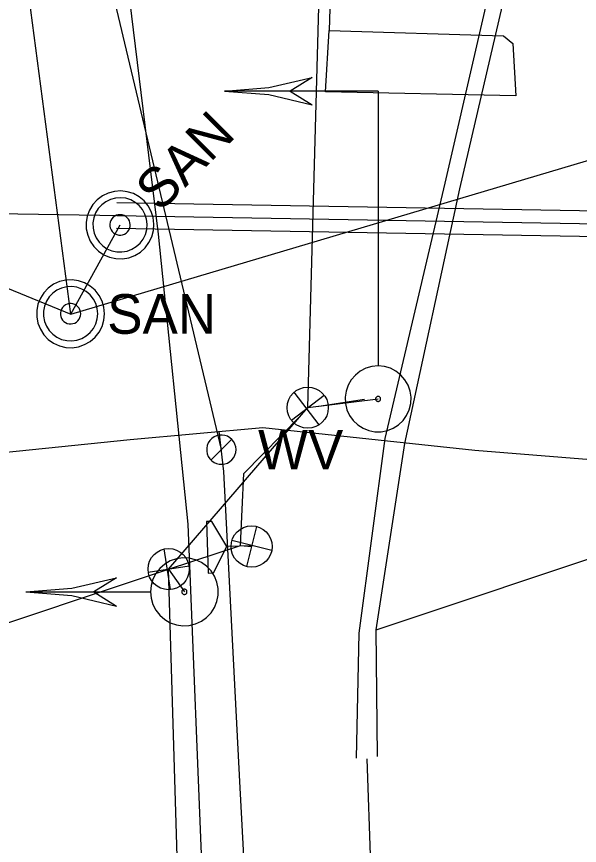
# Model space of a CAD drawing. Extents: x 596028 to 606371, y 330010 to 403088.
# Drawn here: x 605075.1 to 605129.8, y 337934.3 to 338014.8 of the extents above; entities that cross this region are included whole.
import ezdxf

# ---------------------------------------------------------------- set-up
doc = ezdxf.new("R2010")
doc.units = 0
for name, color, linetype in [('E_SIG', 7, 'Continuous'), ('E_SIG_Conduit', 7, 'Continuous'), ('E_UTL_E_UG', 7, 'Continuous'), ('E_UTL_FO_UG', 7, 'Continuous'), ('E_UTL_G_UG', 7, 'Continuous'), ('E_UTL_Loop_UG', 7, 'Continuous'), ('E_UTL_SAN_MH', 7, 'Continuous'), ('E_UTL_SAN_UG', 7, 'Continuous'), ('E_UTL_SAN_UG_MMSD', 7, 'Continuous'), ('E_UTL_SAN_UG_OUTER_LIMITS', 7, 'Continuous'), ('E_UTL_TV_UG', 7, 'Continuous'), ('E_UTL_W', 7, 'Continuous'), ('E_UTL_W_UG', 7, 'Continuous')]:
    doc.layers.add(name, color=color, linetype=linetype)

# ---------------------------------------------------------------- blocks, each defined once
blk = doc.blocks.new('_U316')
at = {"layer": 'E_SIG'}
for p, q in [((0, 6.1), (0, -6.1)), ((-6.09, 0.4), (6.1, 0.4))]:
    blk.add_line(p, q, dxfattribs=at)
blk.add_circle((0, 0.01), 6.1, dxfattribs=at)
blk = doc.blocks.new('_U317')
at = {"layer": 'E_SIG'}
for p, q in [((0, 6.1), (0, -6.1)), ((-6.09, 0.4), (6.1, 0.4))]:
    blk.add_line(p, q, dxfattribs=at)
blk.add_circle((0, 0.01), 6.1, dxfattribs=at)
blk = doc.blocks.new('_U310')
at = {"layer": 'E_SIG'}
for p, q in [((0, 6.1), (0, -6.1)), ((-6.09, 0.4), (6.1, 0.4))]:
    blk.add_line(p, q, dxfattribs=at)
blk.add_circle((0, 0.01), 6.1, dxfattribs=at)

msp = doc.modelspace()

# ---------------------------------------------------------------- linework, layer by layer
at = {"layer": 'E_SIG'}
msp.add_line((605097.976, 337963.419), (605095.576, 337963.336), dxfattribs=at)
for points in [[(605095.332, 338007.579), (605099.655, 338007.914), (605103.873, 338008.913)], [(605103.873, 338008.916), (605101.737, 338007.579)], [(605095.332, 338007.579), (605099.655, 338007.243), (605103.873, 338006.244)], [(605110.278, 338007.579), (605095.333, 338007.579)], [(605101.737, 338007.579), (605103.873, 338006.242)], [(605110.278, 338007.579), (605110.278, 337980.94)], [(605110.278, 338000.105), (605110.278, 338000.105)], [(605110.279, 337980.888), (605109.673, 337980.83), (605109.089, 337980.658), (605108.548, 337980.379), (605108.069, 337980.003), (605107.67, 337979.543), (605107.366, 337979.015), (605107.167, 337978.44), (605107.08, 337977.837), (605107.109, 337977.229), (605107.253, 337976.637), (605107.505, 337976.083), (605107.859, 337975.587), (605108.299, 337975.167), (605108.812, 337974.838), (605109.377, 337974.611), (605109.975, 337974.496), (605110.584, 337974.496), (605111.182, 337974.611), (605111.747, 337974.838), (605112.259, 337975.167), (605112.7, 337975.587), (605113.053, 337976.083), (605113.306, 337976.637), (605113.45, 337977.229), (605113.479, 337977.837), (605113.392, 337978.44), (605113.193, 337979.015), (605112.888, 337979.543), (605112.49, 337980.003), (605112.011, 337980.379), (605111.47, 337980.658), (605110.885, 337980.83), (605110.279, 337980.888)], [(605110.279, 337977.93), (605110.233, 337977.925), (605110.188, 337977.912), (605110.147, 337977.891), (605110.11, 337977.862), (605110.08, 337977.827), (605110.056, 337977.786), (605110.041, 337977.742), (605110.035, 337977.696), (605110.037, 337977.65), (605110.048, 337977.605), (605110.067, 337977.562), (605110.094, 337977.524), (605110.128, 337977.492), (605110.167, 337977.467), (605110.21, 337977.45), (605110.256, 337977.441), (605110.303, 337977.441), (605110.348, 337977.45), (605110.392, 337977.467), (605110.431, 337977.492), (605110.464, 337977.524), (605110.491, 337977.562), (605110.511, 337977.605), (605110.522, 337977.65), (605110.524, 337977.696), (605110.517, 337977.742), (605110.502, 337977.786), (605110.479, 337977.827), (605110.448, 337977.862), (605110.412, 337977.891), (605110.37, 337977.912), (605110.326, 337977.925), (605110.279, 337977.93)], [(605088.149, 337958.945), (605088.209, 337958.32), (605088.385, 337957.718), (605088.673, 337957.16), (605089.061, 337956.667), (605089.535, 337956.256), (605090.078, 337955.943), (605090.671, 337955.738), (605091.292, 337955.648), (605091.919, 337955.678), (605092.528, 337955.826), (605093.099, 337956.087), (605093.61, 337956.451), (605094.043, 337956.905), (605094.382, 337957.432), (605094.615, 337958.015), (605094.734, 337958.631), (605094.734, 337959.258), (605094.615, 337959.874), (605094.382, 337960.457), (605094.043, 337960.985), (605093.61, 337961.439), (605093.099, 337961.802), (605092.528, 337962.063), (605091.919, 337962.211), (605091.292, 337962.241), (605090.671, 337962.152), (605090.078, 337961.946), (605089.535, 337961.633), (605089.061, 337961.222), (605088.673, 337960.729), (605088.385, 337960.171), (605088.209, 337959.569), (605088.149, 337958.945)], [(605076.049, 337958.945), (605080.502, 337959.29), (605084.849, 337960.32)], [(605084.849, 337960.318), (605082.648, 337958.946)], [(605076.049, 337958.945), (605080.502, 337958.599), (605084.849, 337957.57)], [(605076.05, 337958.946), (605088.091, 337958.946)], [(605082.648, 337958.946), (605084.849, 337957.569)], [(605091.197, 337958.945), (605091.201, 337958.897), (605091.215, 337958.851), (605091.237, 337958.808), (605091.266, 337958.77), (605091.303, 337958.739), (605091.344, 337958.715), (605091.39, 337958.699), (605091.437, 337958.692), (605091.485, 337958.695), (605091.532, 337958.706), (605091.575, 337958.726), (605091.614, 337958.754), (605091.647, 337958.789), (605091.673, 337958.829), (605091.691, 337958.873), (605091.7, 337958.921), (605091.7, 337958.969), (605091.691, 337959.016), (605091.673, 337959.06), (605091.647, 337959.101), (605091.614, 337959.135), (605091.575, 337959.163), (605091.532, 337959.183), (605091.485, 337959.194), (605091.437, 337959.197), (605091.39, 337959.19), (605091.344, 337959.174), (605091.303, 337959.15), (605091.266, 337959.119), (605091.237, 337959.081), (605091.215, 337959.038), (605091.201, 337958.992), (605091.197, 337958.945)]]:
    msp.add_lwpolyline(points, dxfattribs=at)
msp.add_lwpolyline([(605094.116, 337965.79), (605093.595, 337965.772), (605093.769, 337960.769), (605094.289, 337960.787), (605095.577, 337963.336)], close=True, dxfattribs=at)
at = {"layer": 'E_SIG_Conduit'}
for points in [[(605103.44, 337976.834), (605105.21, 338040.564)], [(605103.44, 337976.834), (605110.28, 337977.684)], [(605104.502, 337976.967), (605108.946, 337977.652)], [(605089.92, 337961.154), (605103.44, 337976.834)], [(605096.91, 337963.454), (605097.23, 337970.434), (605102.7, 337976.014), (605103.44, 337976.834)], [(605089.92, 337961.154), (605096.91, 337963.454), (605097.98, 337963.344)], [(605047.35, 337946.974), (605089.92, 337961.154)], [(605089.92, 337961.154), (605091.45, 337958.944)]]:
    msp.add_lwpolyline(points, dxfattribs=at)
at = {"layer": 'E_UTL_E_UG'}
msp.add_lwpolyline([(605091.971, 337892.476), (605089.92, 337961.154)], dxfattribs=at)
at = {"layer": 'E_UTL_FO_UG'}
msp.add_lwpolyline([(605110.1, 337955.254), (605134.845, 337963.521)], dxfattribs=at)
at = {"layer": 'E_UTL_G_UG'}
for points in [[(604985.13, 338025.804), (604984.31, 338018.124), (604982.82, 338008.484), (604982.14, 337990.424), (604982.27, 337979.474), (604987, 337975.814), (604995.42, 337975.544), (605011.51, 337976.254), (605020.99, 337971.804), (605053.36, 337969.444), (605062.73, 337971.354), (605086.18, 337973.754), (605099.06, 337974.904), (605119.67, 337972.714), (605158.32, 337969.584), (605188.11, 337968.304), (605207.41, 337968.584), (605224.32, 337967.714), (605236.94, 337968.084), (605244.48, 337969.024), (605249.449, 337969.464), (605249.239, 337972.164), (605249.239, 337972.534)], [(605094.31, 337912.064), (605093.27, 337929.444), (605091.82, 337965.534), (605088.93, 337993.674), (605086.15, 338016.474)]]:
    msp.add_lwpolyline(points, dxfattribs=at)
at = {"layer": 'E_UTL_Loop_UG'}
msp.add_line((605105.64, 338018.244), (605105.53, 338013.454), dxfattribs=at)
msp.add_lwpolyline([(605105.53, 338013.454), (605122.47, 338012.934), (605123.39, 338012.194), (605123.65, 338007.124), (605105.18, 338007.504)], close=True, dxfattribs=at)
at = {"layer": 'E_UTL_SAN_MH'}
for points in [[(605087.524, 337996.919), (605087.04, 337997.319), (605086.489, 337997.62), (605085.892, 337997.811), (605085.269, 337997.885), (605084.643, 337997.84), (605084.037, 337997.678), (605083.473, 337997.404), (605082.97, 337997.028), (605082.548, 337996.564), (605082.222, 337996.028), (605082.003, 337995.44), (605081.899, 337994.821), (605081.914, 337994.194), (605082.047, 337993.581), (605082.294, 337993.004), (605082.646, 337992.485), (605083.089, 337992.041), (605083.609, 337991.69), (605084.185, 337991.443), (605084.798, 337991.309), (605085.426, 337991.294), (605086.044, 337991.398), (605086.632, 337991.618), (605087.168, 337991.944), (605087.632, 337992.366), (605088.008, 337992.868), (605088.282, 337993.433), (605088.445, 337994.039), (605088.489, 337994.665), (605088.415, 337995.287), (605088.224, 337995.885), (605087.923, 337996.436), (605087.524, 337996.919)], [(605087.057, 337996.453), (605086.67, 337996.772), (605086.229, 337997.013), (605085.751, 337997.166), (605085.253, 337997.225), (605084.752, 337997.189), (605084.268, 337997.06), (605083.816, 337996.84), (605083.414, 337996.539), (605083.077, 337996.168), (605082.816, 337995.74), (605082.64, 337995.269), (605082.557, 337994.774), (605082.569, 337994.273), (605082.676, 337993.782), (605082.873, 337993.321), (605083.154, 337992.905), (605083.509, 337992.55), (605083.925, 337992.269), (605084.386, 337992.071), (605084.877, 337991.965), (605085.379, 337991.953), (605085.873, 337992.036), (605086.344, 337992.211), (605086.772, 337992.473), (605087.144, 337992.81), (605087.444, 337993.212), (605087.664, 337993.663), (605087.794, 337994.148), (605087.829, 337994.649), (605087.77, 337995.147), (605087.617, 337995.625), (605087.377, 337996.066), (605087.057, 337996.453)], [(605085.89, 337995.286), (605085.745, 337995.406), (605085.58, 337995.496), (605085.401, 337995.553), (605085.214, 337995.576), (605085.026, 337995.562), (605084.844, 337995.514), (605084.675, 337995.431), (605084.524, 337995.319), (605084.398, 337995.179), (605084.3, 337995.019), (605084.234, 337994.842), (605084.203, 337994.657), (605084.207, 337994.468), (605084.247, 337994.285), (605084.321, 337994.112), (605084.427, 337993.956), (605084.56, 337993.823), (605084.716, 337993.717), (605084.889, 337993.643), (605085.073, 337993.603), (605085.261, 337993.599), (605085.446, 337993.63), (605085.623, 337993.696), (605085.783, 337993.793), (605085.923, 337993.92), (605086.036, 337994.071), (605086.118, 337994.24), (605086.166, 337994.422), (605086.18, 337994.61), (605086.158, 337994.796), (605086.1, 337994.976), (605086.01, 337995.141), (605085.89, 337995.286)], [(605083.682, 337985.955), (605083.622, 337986.58), (605083.445, 337987.182), (605083.158, 337987.739), (605082.77, 337988.232), (605082.296, 337988.643), (605081.752, 337988.957), (605081.16, 337989.162), (605080.539, 337989.251), (605079.912, 337989.222), (605079.302, 337989.074), (605078.732, 337988.813), (605078.22, 337988.449), (605077.788, 337987.995), (605077.448, 337987.467), (605077.215, 337986.885), (605077.096, 337986.269), (605077.096, 337985.641), (605077.215, 337985.025), (605077.448, 337984.443), (605077.788, 337983.915), (605078.22, 337983.461), (605078.732, 337983.097), (605079.302, 337982.837), (605079.912, 337982.689), (605080.539, 337982.659), (605081.16, 337982.748), (605081.752, 337982.953), (605082.296, 337983.267), (605082.77, 337983.678), (605083.158, 337984.171), (605083.445, 337984.729), (605083.622, 337985.331), (605083.682, 337985.955)], [(605083.022, 337985.955), (605082.974, 337986.455), (605082.832, 337986.936), (605082.602, 337987.382), (605082.292, 337987.777), (605081.913, 337988.106), (605081.478, 337988.357), (605081.004, 337988.521), (605080.507, 337988.592), (605080.006, 337988.568), (605079.518, 337988.45), (605079.062, 337988.241), (605078.653, 337987.95), (605078.306, 337987.587), (605078.035, 337987.165), (605077.848, 337986.699), (605077.753, 337986.206), (605077.753, 337985.704), (605077.848, 337985.211), (605078.035, 337984.745), (605078.306, 337984.323), (605078.653, 337983.96), (605079.062, 337983.669), (605079.518, 337983.46), (605080.006, 337983.342), (605080.507, 337983.318), (605081.004, 337983.39), (605081.478, 337983.554), (605081.913, 337983.805), (605082.292, 337984.133), (605082.602, 337984.528), (605082.832, 337984.974), (605082.974, 337985.456), (605083.022, 337985.955)], [(605081.372, 337985.955), (605081.354, 337986.143), (605081.301, 337986.323), (605081.214, 337986.49), (605081.098, 337986.638), (605080.956, 337986.762), (605080.793, 337986.856), (605080.615, 337986.917), (605080.429, 337986.944), (605080.241, 337986.935), (605080.058, 337986.891), (605079.887, 337986.813), (605079.733, 337986.703), (605079.603, 337986.567), (605079.502, 337986.409), (605079.432, 337986.234), (605079.396, 337986.049), (605079.396, 337985.861), (605079.432, 337985.676), (605079.502, 337985.502), (605079.603, 337985.343), (605079.733, 337985.207), (605079.887, 337985.098), (605080.058, 337985.02), (605080.241, 337984.975), (605080.429, 337984.966), (605080.615, 337984.993), (605080.793, 337985.055), (605080.956, 337985.149), (605081.098, 337985.272), (605081.214, 337985.42), (605081.301, 337985.587), (605081.354, 337985.768), (605081.372, 337985.955)]]:
    msp.add_lwpolyline(points, dxfattribs=at)
at = {"layer": 'E_UTL_SAN_UG'}
for q in [(605067.643, 338083.076), (605153.517, 338007.635), (605085.19, 337994.584)]:
    msp.add_line((605080.423, 337985.919), q, dxfattribs=at)
msp.add_lwpolyline([(605046.371, 337999.856), (605080.423, 337985.919)], dxfattribs=at)
at = {"layer": 'E_UTL_SAN_UG_MMSD'}
for p, q in [((604679.668, 338002.431), (605085.205, 337995.499)), ((605084.871, 337995.504), (605699.33, 337985.001))]:
    msp.add_line(p, q, dxfattribs=at)
at = {"layer": 'E_UTL_SAN_UG_OUTER_LIMITS'}
for p, q in [((605084.892, 337996.754), (605699.351, 337986.251)), ((605084.849, 337994.255), (605699.309, 337983.751))]:
    msp.add_line(p, q, dxfattribs=at)
at = {"layer": 'E_UTL_TV_UG'}
msp.add_line((605117.511, 337719.769), (605109.201, 337942.73), dxfattribs=at)
for points in [[(605108.19, 337942.804), (605108.43, 337954.924), (605110.98, 337973.854), (605116.8, 337998.644), (605123.14, 338026.194), (605126.02, 338040.874), (605126, 338040.904), (605125.28, 338046.954)], [(605110.21, 337942.944), (605110.1, 337955.254), (605112.87, 337973.354), (605118.22, 337998.074), (605124.68, 338025.804), (605129.14, 338040.474), (605128.12, 338046.924)]]:
    msp.add_lwpolyline(points, dxfattribs=at)
at = {"layer": 'E_UTL_W'}
for points in [[(605096.466, 337972.754), (605096.44, 337973.024), (605096.364, 337973.284), (605096.239, 337973.525), (605096.072, 337973.738), (605095.867, 337973.916), (605095.632, 337974.051), (605095.376, 337974.14), (605095.108, 337974.178), (605094.837, 337974.166), (605094.574, 337974.102), (605094.327, 337973.989), (605094.106, 337973.832), (605093.919, 337973.636), (605093.773, 337973.408), (605093.672, 337973.156), (605093.62, 337972.89), (605093.62, 337972.619), (605093.672, 337972.352), (605093.773, 337972.101), (605093.919, 337971.873), (605094.106, 337971.677), (605094.327, 337971.519), (605094.574, 337971.407), (605094.837, 337971.343), (605095.108, 337971.33), (605095.376, 337971.368), (605095.632, 337971.457), (605095.867, 337971.593), (605096.072, 337971.77), (605096.239, 337971.983), (605096.364, 337972.224), (605096.44, 337972.484), (605096.466, 337972.754)], [(605094.032, 337971.746), (605096.048, 337973.762)]]:
    msp.add_lwpolyline(points, dxfattribs=at)
at = {"layer": 'E_UTL_W_UG'}
for points in [[(605095.04, 337972.754), (605084.561, 338016.897)], [(605099.19, 337892.984), (605098.07, 337917.504), (605096.85, 337940.534), (605095.29, 337970.624), (605094.83, 337974.544)]]:
    msp.add_lwpolyline(points, dxfattribs=at)

# ---------------------------------------------------------------- block references
at = {"layer": 'E_SIG', "xscale": 0.3280833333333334, "yscale": 0.3280833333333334, "rotation": -14.081618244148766}
msp.add_blockref('_U310', (605097.98, 337963.344), dxfattribs=at)
at = {"layer": 'E_SIG_Conduit', "xscale": 0.32808333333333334}
for name, p, yscale, rotation in [('_U316', (605103.44, 337976.834), 0.32808333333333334, 127.52190590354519), ('_U317', (605089.92, 337961.154), 0.3280833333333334, 98.72489939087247)]:
    msp.add_blockref(name, p, dxfattribs=dict(at, yscale=yscale, rotation=rotation))

# ---------------------------------------------------------------- texts
at = {"layer": 'E_UTL_SAN_MH'}
msp.add_text('SAN', height=3.8491, rotation=45, dxfattribs=at).set_placement((605089.086, 337995.73))
msp.add_text('SAN', height=3.8491, dxfattribs=at).set_placement((605083.946, 337984.01))
at = {"layer": 'E_UTL_W'}
msp.add_text('WV', height=3.85, dxfattribs=at).set_placement((605098.605, 337970.829))

doc.saveas('drawing.dxf')
